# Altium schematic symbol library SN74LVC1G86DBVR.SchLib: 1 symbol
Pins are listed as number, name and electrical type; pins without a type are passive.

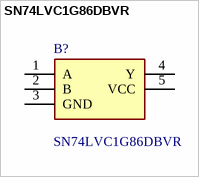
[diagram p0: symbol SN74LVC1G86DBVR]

## SN74LVC1G86DBVR
designator B?
Single 2-Input Exclusive-OR Gate; Manufacturer_Name: Texas Instruments; Geometry.Height: 1.45mm
footprint SOT95P280X145-5N
pins: 1 A, 2 B, 3 GND, 4 Y, 5 VCC (power)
